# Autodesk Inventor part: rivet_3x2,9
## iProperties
Created: 2011-01
Part Number: rivet_3x2,9
Document SubType Name: Modeling
Designer: eric
Density: 1 g/cm^3
Mass: 0.0249003 g
Surface Area: 0.852546 cm^2
Volume: 0.0249003 cm^3
Author: eric
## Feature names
1. Base1
